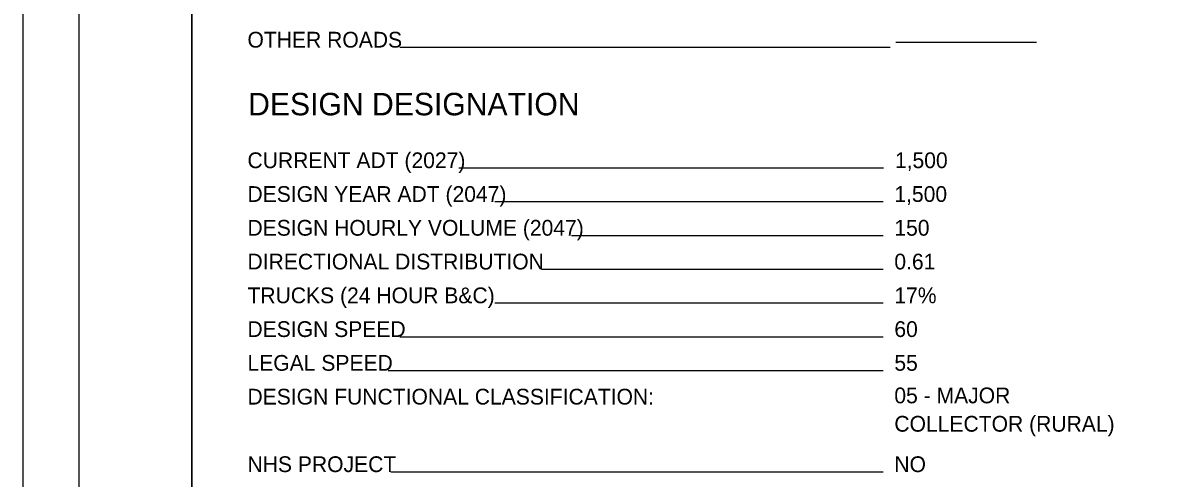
# Model space of a CAD drawing. Extents: x 0 to 34, y 0 to 22.
# Drawn here: x 0 to 10.15, y 7.05 to 11.1 of the extents above; entities that cross this region are included whole.
import ezdxf

# ---------------------------------------------------------------- set-up
doc = ezdxf.new("R2010")
doc.units = 0
for name, color, linetype in [('SH_Border', 7, 'Continuous'), ('SH_Cut_Line', 7, 'Continuous'), ('SH_Data', 7, 'Continuous'), ('SH_Text', 7, 'Continuous')]:
    doc.layers.add(name, color=color, linetype=linetype)

msp = doc.modelspace()

# ---------------------------------------------------------------- linework, layer by layer
at = {"layer": 'SH_Border'}
for points in [[(0.5, 21.5), (1.5, 21.5), (1.5, 0.5), (0.5, 0.5)], [(1.5, 21.5), (33.5, 21.5), (33.5, 0.5), (1.5, 0.5)]]:
    msp.add_lwpolyline(points, close=True, dxfattribs=at)
at = {"layer": 'SH_Cut_Line'}
msp.add_lwpolyline([(0, 0), (34, 0), (34, 22), (0, 22)], close=True, dxfattribs=at)
at = {"layer": 'SH_Data'}
for p, q in [((7.7, 10.877), (3.347, 10.877)), ((9, 10.922), (7.75, 10.922)), ((7.642, 9.806), (3.871, 9.806)), ((7.637, 9.506), (4.189, 9.506)), ((7.637, 9.206), (4.872, 9.206)), ((7.637, 8.906), (4.604, 8.906)), ((7.637, 8.606), (4.189, 8.606)), ((7.637, 8.306), (3.346, 8.306)), ((7.637, 8.006), (3.242, 8.006)), ((7.637, 7.106), (3.267, 7.106))]:
    msp.add_line(p, q, dxfattribs=at)

# ---------------------------------------------------------------- texts
msp.add_text('DESIGN DESIGNATION', height=0.2, dxfattribs=at).set_placement((2, 10.275))
at = {"layer": 'SH_Text'}
for s, p in [('OTHER ROADS', (1.994, 10.877)), ('CURRENT ADT (2027)', (1.994, 9.806)), ('1,500', (7.742, 9.806)), ('DESIGN YEAR ADT (2047)', (1.994, 9.506)), ('1,500', (7.737, 9.506)), ('DESIGN HOURLY VOLUME (2047)', (1.994, 9.206)), ('150', (7.737, 9.206)), ('DIRECTIONAL DISTRIBUTION', (1.994, 8.906)), ('0.61', (7.737, 8.906)), ('TRUCKS (24 HOUR B&C)', (1.994, 8.606)), ('17%', (7.737, 8.606)), ('DESIGN SPEED', (1.994, 8.306)), ('60', (7.737, 8.306)), ('LEGAL SPEED', (1.994, 8.006)), ('55', (7.737, 8.006)), ('DESIGN FUNCTIONAL CLASSIFICATION:', (1.994, 7.706)), ('05 - MAJOR ', (7.737, 7.717)), ('COLLECTOR (RURAL)', (7.737, 7.465)), ('NHS PROJECT', (1.994, 7.106)), ('NO', (7.737, 7.106))]:
    msp.add_text(s, height=0.14, dxfattribs=at).set_placement(p)

doc.saveas('drawing.dxf')
